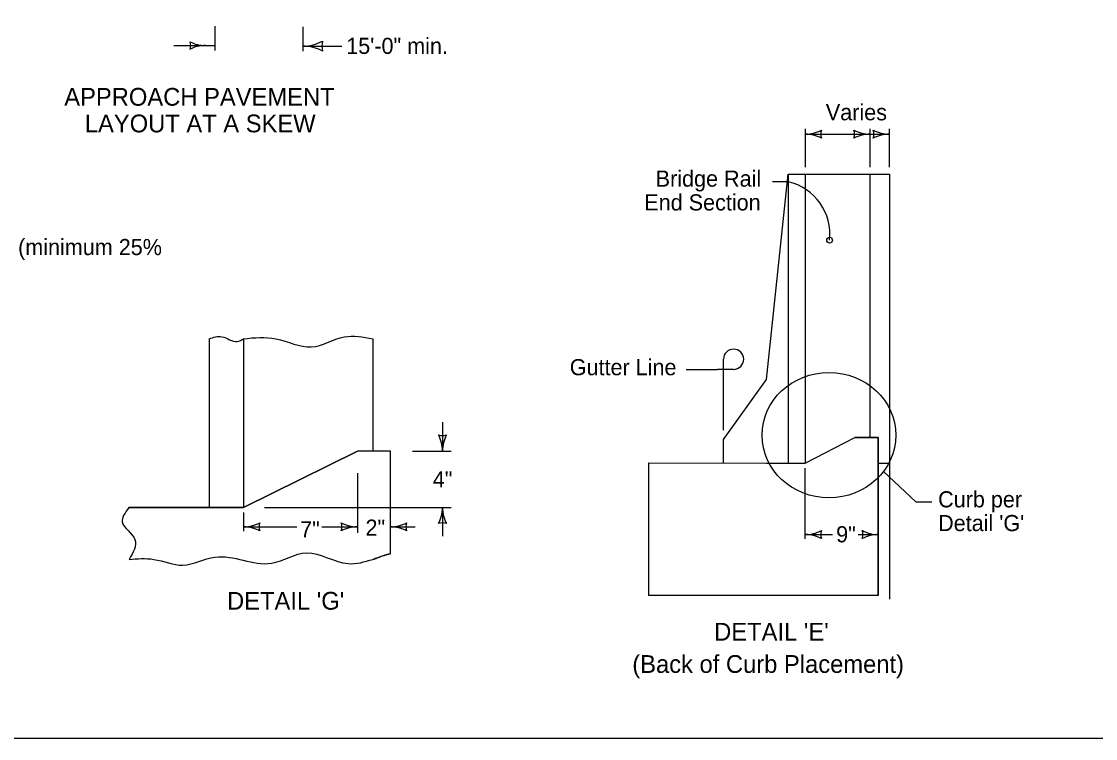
# Model space of a CAD drawing. Extents: x 8925 to 81668, y 4369 to 11918.
# Drawn here: x 18420 to 19752, y 7924 to 8812 of the extents above; entities that cross this region are included whole.
import ezdxf

# ---------------------------------------------------------------- set-up
doc = ezdxf.new("R2010")
doc.units = 0
for name, color, linetype in [('dsnShtPlotShapeBatchPrint', 7, 'Continuous'), ('dsnStdBorder', 7, 'Continuous'), ('Level 3', 7, 'Continuous'), ('Level 5', 7, 'Continuous'), ('SheetBorder', 7, 'Continuous')]:
    doc.layers.add(name, color=color, linetype=linetype)

msp = doc.modelspace()

# ---------------------------------------------------------------- linework, layer by layer
at = {"layer": 'dsnStdBorder'}
for p, q in [((18660.1, 8806.5), (18660.1, 8776.3)), ((18769.1, 8805.7), (18769.1, 8775.6)), ((18609.1, 8782.5), (18660.1, 8782.5)), ((18769.1, 8781.7), (18817.5, 8781.7)), ((19392, 8672.6), (19421.1, 8672.6)), ((19392.3, 8631.9), (19392.3, 8679.3)), ((19392.3, 8672.6), (19472.3, 8672.6)), ((19467.9, 8672.6), (19496.2, 8672.6)), ((19472.3, 8631.9), (19472.3, 8679.3)), ((19496.2, 8631.9), (19496.2, 8679.3)), ((19344, 8368.9), (19370.7, 8622.9)), ((19370.7, 8622.9), (19472, 8622.9)), ((19370.7, 8622.9), (19370.7, 8265.3)), ((19392, 8622.9), (19392, 8265.2)), ((19472, 8622.9), (19472, 8296.8)), ((19472, 8622.9), (19496.2, 8622.9)), ((19496.2, 8622.9), (19496.2, 8096.5)), ((19371, 8613.7), (19351.5, 8613.7)), ((18653.1, 8419.2), (18653.1, 8210.2)), ((18695.7, 8419.2), (18695.7, 8210.2)), ((18855.8, 8419.2), (18855.8, 8280.1)), ((19244.2, 8381.3), (19283.1, 8381.3)), ((19290.6, 8305.9), (19290.6, 8373.8)), ((19290.6, 8294.2), (19344, 8368.9)), ((18855.8, 8336.6), (18855.8, 8280.1)), ((19472, 8328.5), (19472, 8296.8)), ((18942.3, 8315.8), (18942.3, 8280.1)), ((19482.3, 8296.8), (19453.3, 8296.8)), ((19453.3, 8296.8), (19482.3, 8296.8)), ((19482.3, 8101.1), (19482.3, 8296.8)), ((19482.3, 8296.8), (19482.3, 8101.1)), ((19290.6, 8265.2), (19290.6, 8294.2)), ((18877.7, 8280.1), (18837, 8280.1)), ((18877.7, 8152.8), (18877.7, 8280.1)), ((18905.2, 8280.1), (18953, 8280.1)), ((19392, 8171.4), (19392, 8258.7)), ((19482.3, 8265.2), (19496.2, 8265.2)), ((19488.9, 8254.9), (19528.9, 8217.2)), ((18836.8, 8252.8), (18836.8, 8178.9)), ((19528.9, 8217.2), (19548.7, 8217.2)), ((18694.6, 8210.2), (18553.6, 8210.1)), ((18577.9, 8210.1), (18553.6, 8210.1)), ((18553.8, 8210.2), (18599.8, 8210.1)), ((18599.8, 8210.1), (18577.9, 8210.1)), ((18695.7, 8210.1), (18599.8, 8210.1)), ((18599.8, 8210.1), (18695.7, 8210.1)), ((18695.7, 8210.2), (18694.6, 8210.2)), ((18695.7, 8203.8), (18695.7, 8180.8)), ((18721.6, 8210.2), (18953, 8210.2)), ((18942.3, 8210.2), (18942.3, 8174.5)), ((18695.7, 8186.3), (18761.5, 8186.3)), ((18792.8, 8186.3), (18836.8, 8186.3)), ((18877.8, 8186.3), (18908.2, 8186.3)), ((19392, 8176.6), (19425.7, 8176.6)), ((19457.4, 8176.6), (19482.7, 8176.6))]:
    msp.add_line(p, q, dxfattribs=at)
for points in [[(19392, 8265.2), (19453.3, 8296.8)], [(19392, 8265.2), (19453.3, 8296.8)], [(18837, 8280.1), (18695.7, 8210.2), (18695.7, 8210.1)], [(18695.7, 8210.1), (18837, 8280.1)], [(18877.7, 8280.1), (18855.8, 8280.1), (18837, 8280.1)], [(18877.7, 8152.8), (18877.7, 8152.8), (18877.7, 8280.1)], [(19482.3, 8101.1), (19197.9, 8101.1), (19197.9, 8265.3), (19344, 8265.2), (19392, 8265.2)], [(19482.3, 8101.1), (19197.9, 8101.1), (19197.9, 8265.3), (19344, 8265.2), (19392, 8265.2)]]:
    msp.add_lwpolyline(points, dxfattribs=at)
for centre, radius, start, end in [((18614.6, 8782.4), 15.5, 342.2666, 17.7334), ((18648.3, 8822.6), 40.2, 241.9275, 270), ((18769.1, 8833.9), 52.2, 270, 298.0725), ((18812.9, 8781.7), 20.2, 162.2666, 197.7334), ((18648.3, 8742.3), 40.2, 90, 118.0725), ((18769.1, 8729.5), 52.2, 61.9275, 90), ((19355.8, 8548.7), 66.7, 353.5756, 76.8823)]:
    msp.add_arc(centre, radius, start, end, dxfattribs=at)
msp.add_ellipse((19421.3, 8299.8), major_axis=(83, 0), ratio=0.93542, dxfattribs=at)
for points in [[(18653.1, 8419.2), (18668.8, 8421.7), (18687.8, 8415.8), (18695.7, 8419.2)], [(18695.7, 8419.2), (18735.8, 8419.2), (18779.6, 8409.1), (18820.4, 8421.4), (18855.8, 8419.2)], [(18553.6, 8210.1), (18545.3, 8192.5), (18561, 8170.4), (18553.8, 8145.9)], [(18553.6, 8210.1), (18545.3, 8192.5), (18561, 8170.4), (18553.8, 8145.9)], [(18553.8, 8145.9), (18584.4, 8145.9), (18620.5, 8138.8), (18660.2, 8148.8), (18730.2, 8141.2), (18773.9, 8154), (18825.3, 8140.6), (18855.8, 8145.9)], [(18553.8, 8145.9), (18584.4, 8145.9), (18620.5, 8138.8), (18660.2, 8148.8), (18730.2, 8141.2), (18773.9, 8154), (18825.3, 8140.6), (18855.8, 8145.9)], [(18855.8, 8145.9), (18869.8, 8150.9), (18875.1, 8152.5)]]:
    msp.add_spline(points, degree=3, dxfattribs=at)
msp.add_open_spline([(18855.8, 8145.9), (18856.7, 8146.1), (18857.6, 8146.4), (18858.5, 8146.7), (18859.4, 8147), (18860.3, 8147.4), (18861.3, 8147.7), (18863.1, 8148.4), (18864.9, 8149.2), (18866.8, 8149.9), (18868.6, 8150.6), (18870.4, 8151.2), (18872.2, 8151.8), (18873.1, 8152), (18874.1, 8152.2), (18875, 8152.4), (18875.4, 8152.5), (18875.9, 8152.6), (18876.4, 8152.7), (18876.8, 8152.7), (18877.3, 8152.8), (18877.7, 8152.8)], degree=3, dxfattribs=at)
at = {"layer": 'Level 3'}
for centre, radius, start, end in [((19392, 8715.1), 42.5, 270, 298.0725), ((19392, 8630.1), 42.5, 61.9275, 90), ((19427.6, 8672.6), 16.4, 162.2666, 197.7334), ((19436.6, 8672.6), 16.4, 342.2666, 17.7333), ((19472.3, 8715.1), 42.5, 241.9275, 270), ((19472.3, 8630.1), 42.5, 90, 118.0725), ((19460.6, 8672.6), 16.4, 342.2666, 17.7333), ((19496.2, 8715.1), 42.5, 241.9275, 270), ((19496.2, 8630.1), 42.5, 90, 118.0725), ((18942.3, 8315.7), 16.4, 252.2666, 287.7333), ((18899.8, 8280.1), 42.5, 360, 28.0725), ((18984.8, 8280.1), 42.5, 151.9275, 180), ((18899.8, 8210.2), 42.5, 331.9275, 360), ((18984.8, 8210.2), 42.5, 180, 208.0725), ((18695.7, 8228.8), 42.5, 270, 298.0725), ((18731.4, 8186.3), 16.4, 162.2666, 197.7334), ((18801.2, 8186.3), 16.4, 342.2666, 17.7333), ((18836.8, 8228.8), 42.5, 241.9275, 270), ((18877.8, 8228.8), 42.5, 270, 298.0725), ((18913.4, 8186.3), 16.4, 162.2666, 197.7334), ((18942.3, 8174.6), 16.4, 72.2666, 107.7334), ((18695.7, 8143.8), 42.5, 61.9275, 90), ((18836.8, 8143.8), 42.5, 90, 118.0725), ((18877.8, 8143.8), 42.5, 61.9275, 90), ((19392, 8219.1), 42.5, 270, 298.0725), ((19392, 8134.1), 42.5, 61.9275, 90), ((19427.6, 8176.6), 16.4, 162.2666, 197.7334), ((19447, 8176.6), 16.4, 342.2666, 17.7333), ((19482.7, 8219.1), 42.5, 241.9275, 270), ((19482.7, 8134.1), 42.5, 90, 118.0725)]:
    msp.add_arc(centre, radius, start, end, dxfattribs=at)
at = {"layer": 'Level 5'}
for p, q in [((19290.6, 8373.8), (19290.6, 8393.8)), ((19303.1, 8381.3), (19283.1, 8381.3))]:
    msp.add_line(p, q, dxfattribs=at)
msp.add_circle((19422.1, 8541.3), 3.54, dxfattribs=at)
msp.add_arc((19303.1, 8393.8), 12.5, 270, 180, dxfattribs=at)
at = {"layer": 'SheetBorder'}
msp.add_lwpolyline([(17332.5, 9944), (20467.5, 9944), (20467.5, 7924), (17332.5, 7924)], close=True, dxfattribs=at)

# ---------------------------------------------------------------- texts
at = {"layer": 'dsnShtPlotShapeBatchPrint'}
for s, height, p in [('15\'-0" min.', 20, (18822.9, 8772)), ('Closed Cell Backer Rod (minimum 25%', 20, (18124.8, 8522.8)), ('(Back of Curb Placement)', 22, (19177.5, 8005.3))]:
    msp.add_text(s, height=height, dxfattribs=at).set_placement(p)
at = {"layer": 'dsnStdBorder'}
for s, height, p in [('APPROACH PAVEMENT', 22, (18473.4, 8707.9)), ('Varies', 20, (19417.4, 8689.8)), ('LAYOUT AT A SKEW', 22, (18498.9, 8674.9)), ('Bridge Rail ', 20, (19206.5, 8607.6)), ('End Section', 20, (19192.4, 8578.1)), ('Gutter Line', 20, (19100, 8374)), ('4"', 20, (18930.2, 8235.1)), ('Curb per', 20, (19556.6, 8210.3)), ("Detail 'G'", 20, (19556.6, 8180.9)), ('7"', 20, (18765.8, 8173.2)), ('2"', 20, (18846.8, 8175.2)), ('9"', 20, (19430.2, 8167)), ("DETAIL 'G'", 22, (18675.2, 8083.6)), ("DETAIL 'E'", 22, (19279, 8045.3))]:
    msp.add_text(s, height=height, dxfattribs=at).set_placement(p)

doc.saveas('drawing.dxf')
